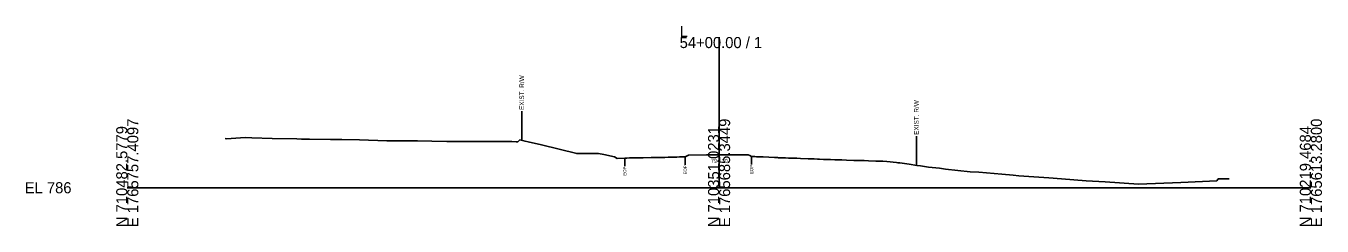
# Model space of a CAD drawing. Extents: x -26 to 5303, y -10 to 9578.
# Drawn here: x 3974.3 to 4302.8, y 3990.3 to 4040.9 of the extents above; entities that cross this region are included whole.
import ezdxf

# ---------------------------------------------------------------- set-up
doc = ezdxf.new("R2010")
doc.units = 0
for name, color, linetype in [('Exist Cross Section Cell', 7, 'Continuous'), ('Exist XS Ground Line', 7, 'Continuous'), ('Old_Level_10', 7, 'Continuous'), ('Old_Level_3', 7, 'Continuous')]:
    doc.layers.add(name, color=color, linetype=linetype)

msp = doc.modelspace()

# ---------------------------------------------------------------- linework, layer by layer
at = {"layer": 'Exist Cross Section Cell'}
for p, q in [((4150, 4000), (4150, 4038.13)), ((4000, 4000), (4150, 4000)), ((4150, 4000), (4300, 4000))]:
    msp.add_line(p, q, dxfattribs=at)
at = {"layer": 'Exist XS Ground Line'}
msp.add_lwpolyline([(4024.84, 4012.43), (4025.18, 4012.41), (4029.87, 4012.69), (4031.57, 4012.63), (4036.75, 4012.47), (4042.97, 4012.35), (4044.12, 4012.32), (4046.21, 4012.29), (4051.49, 4012.19), (4054.38, 4012.17), (4058.85, 4012.14), (4065.78, 4011.89), (4067.03, 4011.87), (4073.59, 4011.85), (4077.18, 4011.8), (4080.96, 4011.71), (4092.59, 4011.66), (4097.48, 4011.66), (4098.58, 4011.6), (4098.98, 4011.58), (4099.48, 4012.08), (4100.83, 4011.76), (4101.62, 4011.59), (4104.95, 4010.86), (4113.94, 4008.64), (4115.22, 4008.64), (4119.44, 4008.64), (4120.82, 4008.39), (4123.5, 4007.85), (4124.14, 4007.4), (4126.08, 4007.51), (4126.63, 4007.52), (4127.3, 4007.54), (4129.79, 4007.57), (4130.75, 4007.6), (4132.8, 4007.62), (4135.49, 4007.65), (4136.27, 4007.67), (4137.08, 4007.71), (4137.49, 4007.72), (4138.24, 4007.73), (4139.32, 4007.77), (4139.96, 4007.79), (4140.72, 4007.81), (4141.41, 4007.82), (4142.27, 4008.25), (4146.85, 4008.28), (4150, 4008.3), (4157.37, 4008.35), (4157.77, 4008.16), (4158.25, 4007.91), (4159.06, 4007.86), (4159.46, 4007.85), (4160.22, 4007.8), (4161.14, 4007.78), (4164.06, 4007.63), (4164.78, 4007.62), (4165.09, 4007.6), (4165.67, 4007.57), (4166.17, 4007.55), (4166.84, 4007.53), (4167.58, 4007.51), (4168.93, 4007.48), (4169.69, 4007.46), (4170.62, 4007.42), (4172.55, 4007.35), (4173.11, 4007.32), (4174.13, 4007.28), (4174.95, 4007.24), (4175.49, 4007.22), (4176.46, 4007.18), (4176.8, 4007.16), (4178.25, 4007.1), (4179.34, 4007.07), (4180.47, 4007.04), (4181.1, 4007.03), (4182.32, 4007), (4184.16, 4006.93), (4184.54, 4006.92), (4186.8, 4006.87), (4187.84, 4006.83), (4189.75, 4006.76), (4191.48, 4006.74), (4192.5, 4006.66), (4194.95, 4006.37), (4195.35, 4006.32), (4195.84, 4006.26), (4198.2, 4005.94), (4200.15, 4005.64), (4201.05, 4005.51), (4202.57, 4005.31), (4203.1, 4005.23), (4205.91, 4004.91), (4207.35, 4004.71), (4213.61, 4004.02), (4215.85, 4003.95), (4221.65, 4003.45), (4224.56, 4003.2), (4225.96, 4003.05), (4233.57, 4002.5), (4236.83, 4002.24), (4243.04, 4001.72), (4247.85, 4001.47), (4256.27, 4000.93), (4267.06, 4001.33), (4276.13, 4001.73), (4276.54, 4002.23), (4279.3, 4002.24)], dxfattribs=at)
at = {"layer": 'Old_Level_10'}
for p, q in [((4099.99, 4019.36), (4099.99, 4011.96)), ((4200, 4013.07), (4200, 4005.67)), ((4126.08, 4007.51), (4126.08, 4005.45)), ((4141.41, 4007.82), (4141.41, 4005.77)), ((4158.25, 4007.91), (4158.25, 4005.86))]:
    msp.add_line(p, q, dxfattribs=at)

# ---------------------------------------------------------------- texts
at = {"layer": 'Exist Cross Section Cell'}
for s, p in [('54+00.00 / 1', (4140, 4035.33)), ('L', (4140, 4038.13)), ('EL 786', (3974, 3998.6))]:
    msp.add_text(s, height=2.8, dxfattribs=at).set_placement(p)
for s, p in [('N 710482.5779', (4000, 3990)), ('E 1765757.4097', (4002.8, 3990)), ('N 710351.0231', (4150, 3990)), ('E 1765685.3449', (4152.8, 3990)), ('N 710219.4684', (4300, 3990)), ('E 1765613.2800', (4302.8, 3990))]:
    msp.add_text(s, height=2.8, rotation=90, dxfattribs=at).set_placement(p)
at = {"layer": 'Old_Level_10'}
for s, height, p in [('EXIST. R/W', 1.181, (4100.58, 4019.66)), ('EXIST. R/W', 1.181, (4200.59, 4013.37)), ('EOP', 0.787, (4126.48, 4003.06)), ('EOP', 0.787, (4141.8, 4003.37)), ('EOP', 0.787, (4158.64, 4003.46))]:
    msp.add_text(s, height=height, rotation=90, dxfattribs=at).set_placement(p)
at = {"layer": 'Old_Level_3'}
msp.add_text('794.30', height=1, dxfattribs=at).set_placement((4147.95, 4006.3))

doc.saveas('drawing.dxf')
